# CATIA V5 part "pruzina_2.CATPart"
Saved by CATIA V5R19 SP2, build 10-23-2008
Part number: Pruzina delka 21mm
Bounding box of the stored display mesh (mm): x -8 to 8, y -8 to 8, z 0 to 21
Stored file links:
  D:\DURATEC\pruzina_2.CATPart
  D:\DURATEC\pruzina_1.CATPart
  D:\DURATEC\Pohyb pruziny.CATProduct
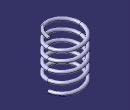
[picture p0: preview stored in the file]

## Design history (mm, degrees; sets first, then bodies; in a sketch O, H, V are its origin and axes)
External parameters (linked from other documents)
  `External.Delka pruziny` = 21 mm
  `External.Pocet zavitu` = 5
  `External.Vnitrni prumer pruziny` = 13 mm
  `External.Prumer dratu` = 1.5 mm
Set1
  Plane1: type Normal, Curve {line type PtDir, Direction (0, 0, 1), Start 0, End 21 {= `External.Delka pruziny`}, RefPoint {point type Coord, X 0, Y 0, Z 0}}, RefPoint vertex of Plane1
  Sketch1 on zx-plane, origin (0, 0, 0), H (-1, 0, 0), V (0, 0, 1)
    line L1 (6.5, 20) -> (6.5, 15)
    construction line L2 (6.5, 15) -> (-6.5, 15)
    line L3 (-6.5, 15) -> (-6.5, 20)
    construction line L4 (-6.5, 20) -> (6.5, 20)
    reference intersected line E1 through (0, 21) direction (-1, 0) from Plane1
    distance L3 L1 = 13 {= `External.Vnitrni prumer pruziny`}
    length L1 = 5
    distance L4 E1 = 1
    vertical: L1 V, L3 V
    horizontal: L2 H, L4 H
    equidistance: L1 L3 O
  Line1: type PtDir, Direction (0, 0, 1), Start 0, End 21 {= `External.Delka pruziny`}, RefPoint {point type Coord, X 0, Y 0, Z 0}
Body1 "Pruzina" (main body)
  Helix1: Pitch 4.2 {= `External.Delka pruziny` /`External.Pocet zavitu`}, TaperAngle 0, Height 21 {= Plane1.End}, Direction {line type PtDir, Direction (0, 0, 1), Start 0, End 21 {= `External.Delka pruziny`}, RefPoint {point type Coord, X 0, Y 0, Z 0}}, RefPoint {point type Coord, X 7.25 {= `External.Vnitrni prumer pruziny` /2+`External.Prumer dratu` /2}, Y 0, Z 0}
  Sketch2 on zx-plane, origin (0, 0, 0), H (-1, 0, 0), V (0, 0, 1)
    circle A1 centre (-7.25, 0) radius 0.75
    point P1 (-7.25, 0)
    reference projected point E1 (-7.25, 0) from vertex of Helix1
    radius A1 = 0.75 {= `External.Prumer dratu` /2}
    distance V A1 = 6.5 (reference)
    distance V A1 = 8 (reference)
    coincidence: P1 E1
  Rib1: profile Sketch2, centre curve Helix1
  Split1: SplitPlane xy-plane
  Split2: SplitPlane Plane1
